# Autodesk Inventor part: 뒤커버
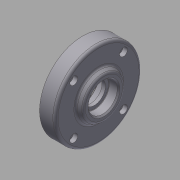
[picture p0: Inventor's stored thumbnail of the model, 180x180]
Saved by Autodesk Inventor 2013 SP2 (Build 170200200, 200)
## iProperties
Company: 한국ATC센터
Created: 2015-12
Part Number: 뒤커버
Document SubType Name: Modeling
Designer: mdu
Density: 2.71 g/cm^3
Mass: 97.9591 g
Surface Area: 115.525 cm^2
Volume: 36.1473 cm^3
Material: 알루미늄-6061
Author: mdu
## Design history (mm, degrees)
sketch "스케치1"
  geometry: L1 (-10.5, 0)-(10.5, 0); L2 (10.5, 0)-(10.5, 22.5); L3 (10.5, 22.5)-(5.5, 22.5); L4 (5.5, 22.5)-(5.5, 32.5); L5 (5.5, 32.5)-(-6.5, 32.5); L6 (-6.5, 32.5)-(-6.5, 17.5); L7 (-6.5, 17.5)-(-10.5, 15.191); L8 (-10.5, 15.191)-(-10.5, 0); 2 further points
  constraints: 16 end point, 3 parallel, 3 perpendicular, 1 coincident, 1 horizontal, 1 midpoint
  dimensions: "d0" = 21 distance of L1.start L1.end; "d1" = 65 diameter of L5 L1; "d2" = 45 diameter of L3 L1; "d3" = 35 diameter of L6.end L1; "d4" = 120 deg angle of L7 L6; "d5" = 12 distance of L4.end L5.end; "d6" = 5 distance of L2.end L3.end
revolve "회전1" sketch "스케치1" stored, may be unused: angle "d7" = 90 deg
sketch "스케치2"
  geometry: L1 (0, 0)-(32.5, 0); L2 (0, 0)-(18.738, 18.738); 1 further point
  constraints: 4 end point, 1 horizontal, 1 horizontal alignment, 1 other
  dimensions: "d8" = 45 deg angle of L1 L2; "d9" = 26.5 distance of L1.start L2.end
hole "구멍1" sketch "스케치2" at (18.738, 18.738) diameter "d10" = 3.4; stored, may be unused: countersink angle "d14" = 90 deg, drill point angle "d16" = 118 deg; dims "d11" = 6, "d12" = 6, "d13" = 3.3, "d15" = 8
fillet "모깎기1" dims "d20" = 2
hole "구멍2" diameter "d23" = 15; stored, may be unused: countersink angle "d27" = 90 deg, drill point angle "d29" = 0 deg; dims "d21" = 10, "d22" = 10, "d24" = 6, "d25" = 35, "d26" = 11, "d28" = 14
chamfer "모따기1" distance "d39" = 1; stored, may be unused: second distance "d40" = 2, angle "d41" = 45 deg
fillet "모깎기2" dims "d42" = 0.3
hole "구멍4" diameter "d46" = 17; stored, may be unused: countersink angle "d50" = 90 deg, drill point angle "d52" = 118 deg; dims "d44" = 10, "d45" = 10, "d47" = 6, "d48" = 22, "d49" = 7.3, "d51" = 8
chamfer "모따기2" distance "d53" = 1; stored, may be unused: second distance "d54" = 2, angle "d55" = 45 deg
fillet "모깎기3" dims "d56" = 0.3
node "솔리드1"
pattern_circular "원형 패턴1" dims angle "d18" = 360 deg
